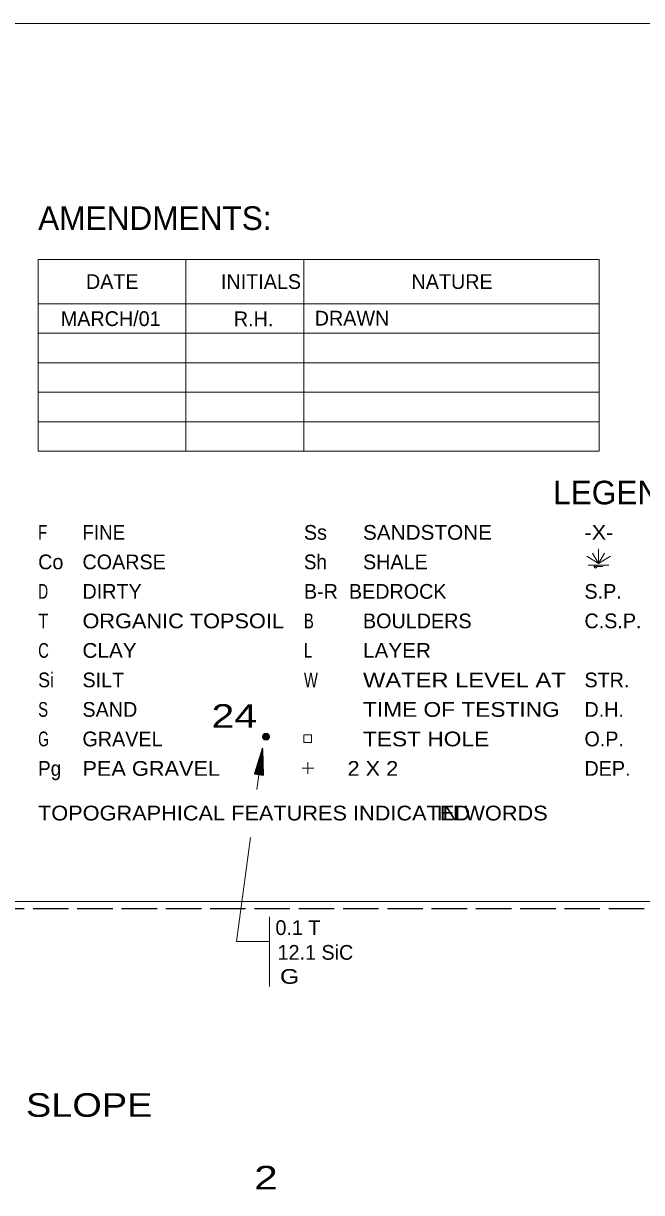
# Model space of a CAD drawing. Extents: x -496 to 480, y -450 to 700.
# Drawn here: x 5 to 214.3, y 303.7 to 700 of the extents above; entities that cross this region are included whole.
import ezdxf
from ezdxf.enums import TextEntityAlignment as Align

# ---------------------------------------------------------------- set-up
doc = ezdxf.new("R2010")
doc.units = 0
doc.header["$LTSCALE"] = 2
doc.header["$PDMODE"] = 32
doc.header["$PDSIZE"] = 1
doc.linetypes.add('LONG_DASHED', pattern=[7.5, 6, -1.5])
for name, color, linetype, lineweight in [('1', 7, 'Continuous', 13), ('2', 7, 'Continuous', 35), ('4', 7, 'Continuous', 25)]:
    doc.layers.add(name, color=color, linetype=linetype, lineweight=lineweight)

msp = doc.modelspace()

# ---------------------------------------------------------------- linework, layer by layer
at = {"layer": '1'}
for p, q in [((199.983, 619.973), (9.983, 619.973)), ((9.983, 619.973), (9.983, 554.973)), ((59.983, 619.973), (59.983, 554.973)), ((99.983, 619.973), (99.983, 554.973)), ((199.983, 554.973), (199.983, 619.973)), ((9.983, 604.973), (199.983, 604.973)), ((9.983, 594.973), (199.983, 594.973)), ((9.983, 584.973), (199.983, 584.973)), ((9.983, 574.973), (199.983, 574.973)), ((9.983, 564.973), (199.983, 564.973)), ((199.76, 516.875), (195.76, 519.375)), ((199.76, 516.875), (197.76, 520.375)), ((199.76, 516.875), (199.76, 521.875)), ((199.76, 516.875), (201.76, 520.375)), ((199.76, 516.875), (203.76, 519.375)), ((196.26, 516.375), (203.26, 516.375)), ((198.26, 515.875), (201.26, 515.875)), ((101.291, 449.597), (101.291, 445.597)), ((103.353, 447.618), (99.353, 447.618))]:
    msp.add_line(p, q, dxfattribs=at)
for points in [[(449.983, -450.027), (449.983, 399.973), (449.983, 699.973), (-450.017, 699.973), (-450.017, 49.973), (-450.017, -450.027)], [(9.983, 554.973), (99.983, 554.973), (199.983, 554.973)], [(402.281, -402.333), (402.281, 402.339), (-402.391, 402.339)]]:
    msp.add_lwpolyline(points, dxfattribs=at)
msp.add_lwpolyline([(99.967, 456.301), (99.967, 458.832), (102.499, 458.832), (102.499, 456.301)], close=True, dxfattribs=at)
msp.add_point((198.76, 515.875), dxfattribs=at)
at = {"layer": '2', "lineweight": 13}
for p, q in [((84.079, 440.317), (85.973, 454.323)), ((88.366, 373.545), (88.366, 397.205))]:
    msp.add_line(p, q, dxfattribs=at)
at = {"layer": '2', "linetype": 'LONG_DASHED', "lineweight": 25}
msp.add_line((-126.758, 400), (287.237, 400), dxfattribs=at)
at = {"layer": '2', "lineweight": 25}
msp.add_lwpolyline([(85.973, 454.323), (83.281, 445.606), (86.253, 445.204)], close=True, dxfattribs=at)
msp.add_lwpolyline([(83.378, 445.666), (85.915, 453.897), (86.148, 445.341), (83.512, 445.682), (85.841, 453.35), (86.04, 445.503), (83.641, 445.794), (85.762, 452.771), (85.898, 445.669), (83.814, 445.869), (85.658, 452.116), (85.777, 445.866), (83.998, 446.009), (85.534, 451.33), (85.604, 446.037), (84.212, 446.143), (85.404, 450.481), (85.391, 446.278), (84.414, 446.312), (85.229, 449.555), (85.233, 446.56), (84.639, 446.527), (85.095, 448.444), (85, 446.886)], dxfattribs=at)
at = {"layer": '2', "lineweight": 13}
msp.add_lwpolyline([(88.126, 388.84), (77.12, 388.84), (81.879, 424.04)], dxfattribs=at)
at = {"layer": '2'}
msp.add_circle((87.142, 458.25), 1, dxfattribs=at)
msp.add_spline([(87.131, 459.137), (87.861, 458.733), (88.013, 457.885), (87.328, 457.357), (86.519, 457.587), (86.232, 458.345), (86.479, 458.907), (87.052, 459.075), (87.726, 458.581), (87.71, 457.84), (87.193, 457.581), (86.67, 457.75), (86.446, 458.396), (87.03, 458.862), (87.468, 458.328), (87.429, 457.845), (86.8, 457.98), (86.946, 458.615), (87.238, 458.064)], degree=3, dxfattribs=at)

# ---------------------------------------------------------------- texts
at = {"layer": '1'}
for s, height, p in [('AMENDMENTS:', 8, (9.983, 629.973)), ('Ss', 5, (99.983, 524.973)), ('Co', 5, (9.983, 514.973)), ('COARSE', 5, (24.983, 514.973)), ('SHALE', 5, (119.983, 514.973)), ('DIRTY', 5, (24.983, 504.973)), ('B-R  BEDROCK', 5, (99.983, 504.973)), ('S.P.', 5, (194.983, 504.973)), ('BOULDERS', 5, (119.983, 494.973)), ('C.S.P.', 5, (194.983, 494.973)), ('SILT', 5, (24.983, 474.973)), ('STR.', 5, (194.983, 474.973)), ('SAND', 5, (24.983, 464.973)), ('D.H.', 5, (194.983, 464.973)), ('GRAVEL', 5, (24.983, 454.973)), ('O.P.', 5, (194.983, 454.973)), ('DEP.', 5, (194.983, 444.973))]:
    msp.add_text(s, height=height, dxfattribs=at).set_placement(p)
for s, height, p in [('DATE', 5, (35.081, 609.973)), ('INITIALS', 5, (85.453, 609.973)), ('NATURE', 5, (150.16, 609.973)), ('MARCH/01', 5, (34.552, 597.405)), ('R.H.', 5, (82.941, 597.343)), ('DRAWN', 5, (116.266, 597.567)), ('LEGEND', 8, (206.378, 536.973))]:
    msp.add_text(s, height=height, dxfattribs=at).set_placement(p, align=Align.CENTER)
for s, width, p in [('F', 0.75, (9.983, 524.973)), ('FINE', 0.95, (24.983, 524.973)), ('SANDSTONE', 1.05, (119.983, 524.973)), ('-X-', 1.1, (194.983, 524.973)), ('Sh', 0.95, (99.983, 514.973)), ('D', 0.7, (9.983, 504.973)), ('T', 0.85, (9.983, 494.973)), ('ORGANIC TOPSOIL', 1.1, (24.983, 494.973)), ('B', 0.75, (99.983, 494.973)), ('C', 0.75, (9.983, 484.973)), ('CLAY', 1.05, (24.983, 484.973)), ('L', 0.75, (99.983, 484.973)), ('LAYER', 1.05, (119.983, 484.973)), ('Si', 0.9, (9.983, 474.973)), ('W', 0.75, (99.983, 474.973)), ('WATER LEVEL AT', 1.2, (119.983, 474.973)), ('S', 0.75, (9.983, 464.973)), ('TIME OF TESTING', 1.15, (119.983, 464.973)), ('G', 0.7, (9.983, 454.973)), ('TEST HOLE', 1.15, (119.983, 454.973)), ('Pg', 0.95, (9.983, 444.973)), ('PEA GRAVEL', 1.1, (24.983, 444.973)), ('   2 X 2', 1.1, (108.608, 444.973)), ('TOPOGRAPHICAL FEATURES INDICATED', 1.1, (9.942, 429.855)), ('IN WORDS', 1.1, (144.942, 429.855))]:
    msp.add_text(s, height=5, dxfattribs=dict(at, width=width)).set_placement(p)
at = {"layer": '2'}
for s, width, p in [(' 24', 1.3, (84.141, 461.25)), ('  2', 1.35, (91.135, 304.781))]:
    msp.add_text(s, height=8, dxfattribs=dict(at, width=width)).set_placement(p, align=Align.RIGHT)
for s, p in [('0.1 T      ', (90.338, 391.025)), ('12.1 SiC   ', (91.056, 382.635))]:
    msp.add_text(s, height=5, dxfattribs=at).set_placement(p)
at = {"layer": '2', "width": 1.25}
msp.add_text('  G        ', height=5, dxfattribs=at).set_placement((87.227, 374.484))
at = {"layer": '4', "width": 1.2}
msp.add_text('FENCE LINE & TOP OF SLOPE', height=8, dxfattribs=at).set_placement((-44.072, 329.413), align=Align.CENTER)

doc.saveas('drawing.dxf')
